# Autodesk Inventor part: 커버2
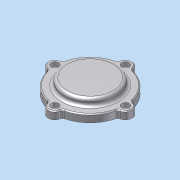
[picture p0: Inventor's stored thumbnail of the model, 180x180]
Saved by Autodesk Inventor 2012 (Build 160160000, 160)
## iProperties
Company: 한국ATC센터
Created: 2015-03
Part Number: 커버2
Document SubType Name: Modeling
Designer: KYOUNG IL JANG
Density: 1 g/cm^3
Material: 기본값
Author: KYOUNG IL JANG
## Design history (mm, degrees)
sketch "스케치1"
  geometry: C1 r 1.621 at (0, 6.75) reference; C2 r 1.621 at (-37, -30.25) reference; C3 r 1.621 at (0, -67.25) reference; C4 r 1.621 at (37, -30.25) reference; C5 r 10 at (0, -30.25) reference; C6 r 12 at (0, -30.25); C7 r 24.5 at (0, -30.25) reference; A1 r 3 centre (-38.77, -20.408) between (-38.239, -23.361) and (-35.862, -21.146) reference; A2 r 7 centre (-37, -30.25) between (-38.239, -23.361) and (-38.239, -37.139) reference; A3 r 3 centre (-38.77, -40.092) between (-35.862, -39.354) and (-38.239, -37.139) reference; A4 r 37 centre (0, -30.25) between (-35.862, -39.354) and (-9.104, -66.113) reference; A5 r 3 centre (-9.842, -69.02) between (-6.889, -68.489) and (-9.104, -66.113) reference; A6 r 7 centre (0, -67.25) between (-6.889, -68.489) and (6.889, -68.489) reference; A7 r 3 centre (9.842, -69.02) between (9.104, -66.112) and (6.889, -68.489) reference; A8 r 37 centre (0, -30.25) between (9.104, -66.112) and (35.863, -39.354) reference; A9 r 3 centre (38.77, -40.092) between (38.239, -37.139) and (35.863, -39.354) reference; A10 r 7 centre (37, -30.25) between (38.239, -37.139) and (38.239, -23.361) reference; A11 r 3 centre (38.77, -20.408) between (35.863, -21.146) and (38.239, -23.361) reference; A12 r 37 centre (0, -30.25) between (35.863, -21.146) and (9.104, 5.612) reference; A13 r 3 centre (9.842, 8.52) between (6.889, 7.989) and (9.104, 5.612) reference; A14 r 7 centre (0, 6.75) between (6.889, 7.989) and (-6.889, 7.989) reference; A15 r 3 centre (-9.842, 8.52) between (-9.104, 5.612) and (-6.889, 7.989) reference; A16 r 37 centre (0, -30.25) between (-9.104, 5.612) and (-35.862, -21.146) reference; 1 further point
  constraints: 1 centre point, 1 coincident
  dimensions: "d2" = 2 radial gap between concentric circles of C6 C5
extrude "돌출1" new body sketch "스케치1" distance "d0" = 8; taper "d1" = 0 deg
sketch "스케치2"
  geometry: C1 r 23.5 at (0, -30.25) reference; C2 r 12 at (0, -30.25) reference; 1 further point
extrude "돌출2" join sketch "스케치2" distance "d4" = 5; taper "d5" = 0 deg
sketch "스케치3"
  geometry: C1 r 23.5 at (0, 0) reference; C2 r 20.5 at (0, 0); 1 further point
  constraints: 1 centre point
  dimensions: "d6" = 3 radial gap between concentric circles of C2 C1
node "작업 평면1"
extrude "돌출3" join sketch "스케치3" stored distance "d7" = 5; taper "d8" = 0 deg
fillet "모깎기1" dims "d9" = 3
sketch "스케치4"
  geometry: C1 r 12 at (0, -30.25) reference; C2 r 27 at (0, -30.25); 1 further point
  constraints: 1 centre point
  dimensions: "d10" = 15 radial gap between concentric circles of C1 C2
extrude "돌출4" join sketch "스케치4" distance "d11" = 7; taper "d12" = 0 deg
fillet "모깎기2" dims "d13" = 3
chamfer "모따기1" distance "d14" = 1; stored, may be unused: second distance "d15" = 2, angle "d16" = 45 deg
node "작업점1"
  node "작업축1"
chamfer "모따기2" distance "d24" = 1; stored, may be unused: second distance "d25" = 2, angle "d26" = 45 deg
hole "구멍6" diameter "d43" = 4.5; stored, may be unused: countersink angle "d47" = 90 deg, drill point angle "d49" = 118 deg; dims "d41" = 10, "d42" = 10, "d44" = 6, "d45" = 8, "d46" = 4.4, "d48" = 8
fillet "모깎기4" dims "d60" = 3
node "솔리드1"
pattern_circular "원형 패턴1" dims angle "d51" = 360 deg
node "참조1"
node "참조2"
